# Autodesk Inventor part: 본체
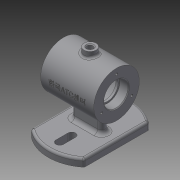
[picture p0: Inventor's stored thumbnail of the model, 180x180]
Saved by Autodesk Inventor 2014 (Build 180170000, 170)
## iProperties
Created: 2017-12
Part Number: 본체
Material: Generic
Document SubType Name: Modeling
Designer: 거성
Density: 1 g/cm^3
Appearance: Default
Author: 거성
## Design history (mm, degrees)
sketch "스케치1"
  geometry: L1 (35, -42.426)-(35, 42.426); L2 (-35, -42.426)-(-35, 42.426); A1 r 55 centre (0, 0) between (-35, -42.426) and (35, -42.426); A2 r 55 centre (0, 0) between (35, 42.426) and (-35, 42.426); 1 further point
  constraints: 4 end point, 4 point on circle, 2 centre point, 1 coincident, 1 concentric, 1 parallel, 1 vertical
  dimensions: "d1" = 70 distance between parallel lines of L2 L1; "d2" = 35 distance from line of point (0, 0) L2; "d3" = 55 radius of A1
extrude "돌출1" new body sketch "스케치1" distance "d4" = 10; taper "d5" = 0 deg
sketch "스케치2"
  geometry: L1 (-35, 42.426)-(-35, -42.426) reference; L2 (35, -42.426)-(35, 42.426) reference; L3 (0, 40)-(0, 24); L4 (-5, 40)-(-5, 24); L5 (5, 24)-(5, 40); A1 r 55 centre (0, 0) between (-35, -42.426) and (35, -42.426) reference; A2 r 55 centre (0, 0) between (35, 42.426) and (-35, 42.426) reference; A3 r 5 centre (0, 40) between (5, 40) and (-5, 40); A4 r 5 centre (0, 24) between (-5, 24) and (5, 24); 1 further point
  constraints: 8 end point, 4 point on circle, 4 tangent, 2 centre point, 2 parallel, 1 midpoint, 1 vertical alignment
  dimensions: "d6" = 16 distance of L5.start L5.end; "d7" = 5 radius of A3; "d8" = 24 distance of L3.end A1.centre
extrude "돌출2" cut sketch "스케치2" distance "d9" = 10; taper "d10" = 0 deg
sketch "스케치3"
  geometry: 1 further point
fillet "모깎기2" dims "d12" = 3
fillet "모깎기3" dims "d13" = 3
sketch "스케치4"
  geometry: L1 (35, 62)-(-35, 62); L2 (-35, 62)-(-35, 92); L3 (-35, 92)-(35, 92); L4 (35, 92)-(35, 62); L5 (33.846, 0)-(-33.846, 0) reference; 3 further points
  constraints: 8 end point, 2 midpoint, 2 parallel, 1 horizontal, 1 perpendicular, 1 vertical alignment
  dimensions: "d14" = 70 distance of L2.end L3.end; "d15" = 30 distance of L1.end L2.end; "d16" = 62 distance between parallel lines of L1 L5
revolve "회전1" sketch "스케치4" stored, may be unused: angle "d17" = 90 deg
sketch "스케치5"
  geometry: L1 (35, 32)-(35, 92) reference; L2 (-35, 32)-(-35, 92) reference; L3 (-35, 92)-(35, 92) reference; L4 (-35, 32)-(35, 32) reference; L5 (-35, 62)-(35, 62); L6 (-35, 78)-(-23, 78); L7 (-23, 78)-(-23, 76); L8 (-23, 76)-(-20, 76); L9 (-20, 76)-(-20, 87); L10 (-20, 87)-(20, 87); L11 (20, 87)-(20, 76); L12 (20, 76)-(23, 76); L13 (23, 76)-(23, 78); L14 (23, 78)-(35, 78); L15 (35, 62)-(35, 78); L16 (-35, 78)-(-35, 62); 1 further point
  constraints: 24 end point, 8 parallel, 3 perpendicular, 2 midpoint, 2 point on line
  dimensions: "d18" = 40 distance of L9.end L10.end; "d19" = 12 distance of L6.start L6.end; "d20" = 12 distance of L13.end L14.end; "d21" = 3 distance of L7.end L8.end; "d22" = 32 diameter of L6 L5; "d23" = 28 diameter of L8 L5; "d24" = 28 diameter of L12 L5; "d25" = 32 diameter of L14 L5; "d26" = 50 diameter of L10 L5
revolve "회전2" sketch "스케치5" stored, may be unused: angle "d27" = 90 deg
fillet "모깎기4" dims "d28" = 0.3
chamfer "모따기1" distance "d29" = 1; stored, may be unused: second distance "d30" = 2, angle "d31" = 45 deg
sketch "스케치6"
  geometry: L1 (-32, -40.988)-(-32, 40.988) reference; L2 (-15, 0)-(15, 0); L3 (-15, 5)-(15, 5); L4 (15, -5)-(-15, -5); A1 r 52 centre (0, 0) between (32, 40.988) and (-32, 40.988) reference; A2 r 5 centre (-15, 0) between (-15, 5) and (-15, -5); A3 r 5 centre (15, 0) between (15, -5) and (15, 5); 1 further point
  constraints: 8 end point, 4 point on circle, 4 tangent, 2 centre point, 1 coincident, 1 midpoint, 1 parallel, 1 perpendicular
  dimensions: "d32" = 5 radius of A2; "d33" = 30 distance of L2.end L2.start
extrude "돌출3" join sketch "스케치6" stored distance "d34" = 10; taper "d35" = 0 deg
fillet "모깎기5" dims "d36" = 5
node "작업 평면1"
sketch "스케치7"
  geometry: L1 (-35, 30)-(-35, -30) reference; C1 r 8 at (0, 0); 1 further point
  constraints: 1 centre point, 1 coincident
  dimensions: "d38" = 16 diameter of C1
extrude "돌출4" join sketch "스케치7" stored distance "d39" = 18.575; taper "d40" = 0 deg
sketch "스케치8"
  geometry: C1 r 8 at (0, 0) reference; C2 r 4 at (0, 0)
  constraints: 1 centre point, 1 coincident
  dimensions: "d41" = 8 diameter of C2
extrude "돌출5" cut sketch "스케치8" stored distance "d42" = 10; taper "d43" = 0 deg
chamfer "모따기2" distance "d44" = 1; stored, may be unused: second distance "d45" = 2, angle "d46" = 45 deg
sketch "스케치9" dims "d47" = 46
  geometry: C1 r 30 at (0, 0) reference; C2 r 17 at (0, 0) reference; 3 further points
  constraints: 2 vertical alignment, 1 coincident, 2 other
hole "구멍1" sketch "스케치9" at (0, 23) diameter "d48" = 3.242; stored, may be unused: countersink angle "d52" = 90 deg, drill point angle "d54" = 118 deg; dims "d49" = 8, "d50" = 4, "d51" = 2, "d53" = 10
fillet "모깎기6" dims "d58" = 3
node "작업 평면2"
sketch "스케치10"
  geometry: L1 (-35, 92)-(35, 92) reference; L2 (-35, 32)-(-35, 92) reference; 2 further points
  constraints: 1 other
  dimensions: "d60" = 35 distance from line of L2 point (0, 62); "d61" = 30 distance from line of L1 point (0, 62)
feature "엠보싱1" sketch "스케치10" dims "d1" = 70, "d62" = 0.5, "d63" = 0
node "솔리드1"
mirror "대칭1"
pattern_circular "원형 패턴1" dims angle "d56" = 360 deg
mirror "대칭2"
node "투영된 루프1"
other parameters: "d37" = 99, "d59" = 45
